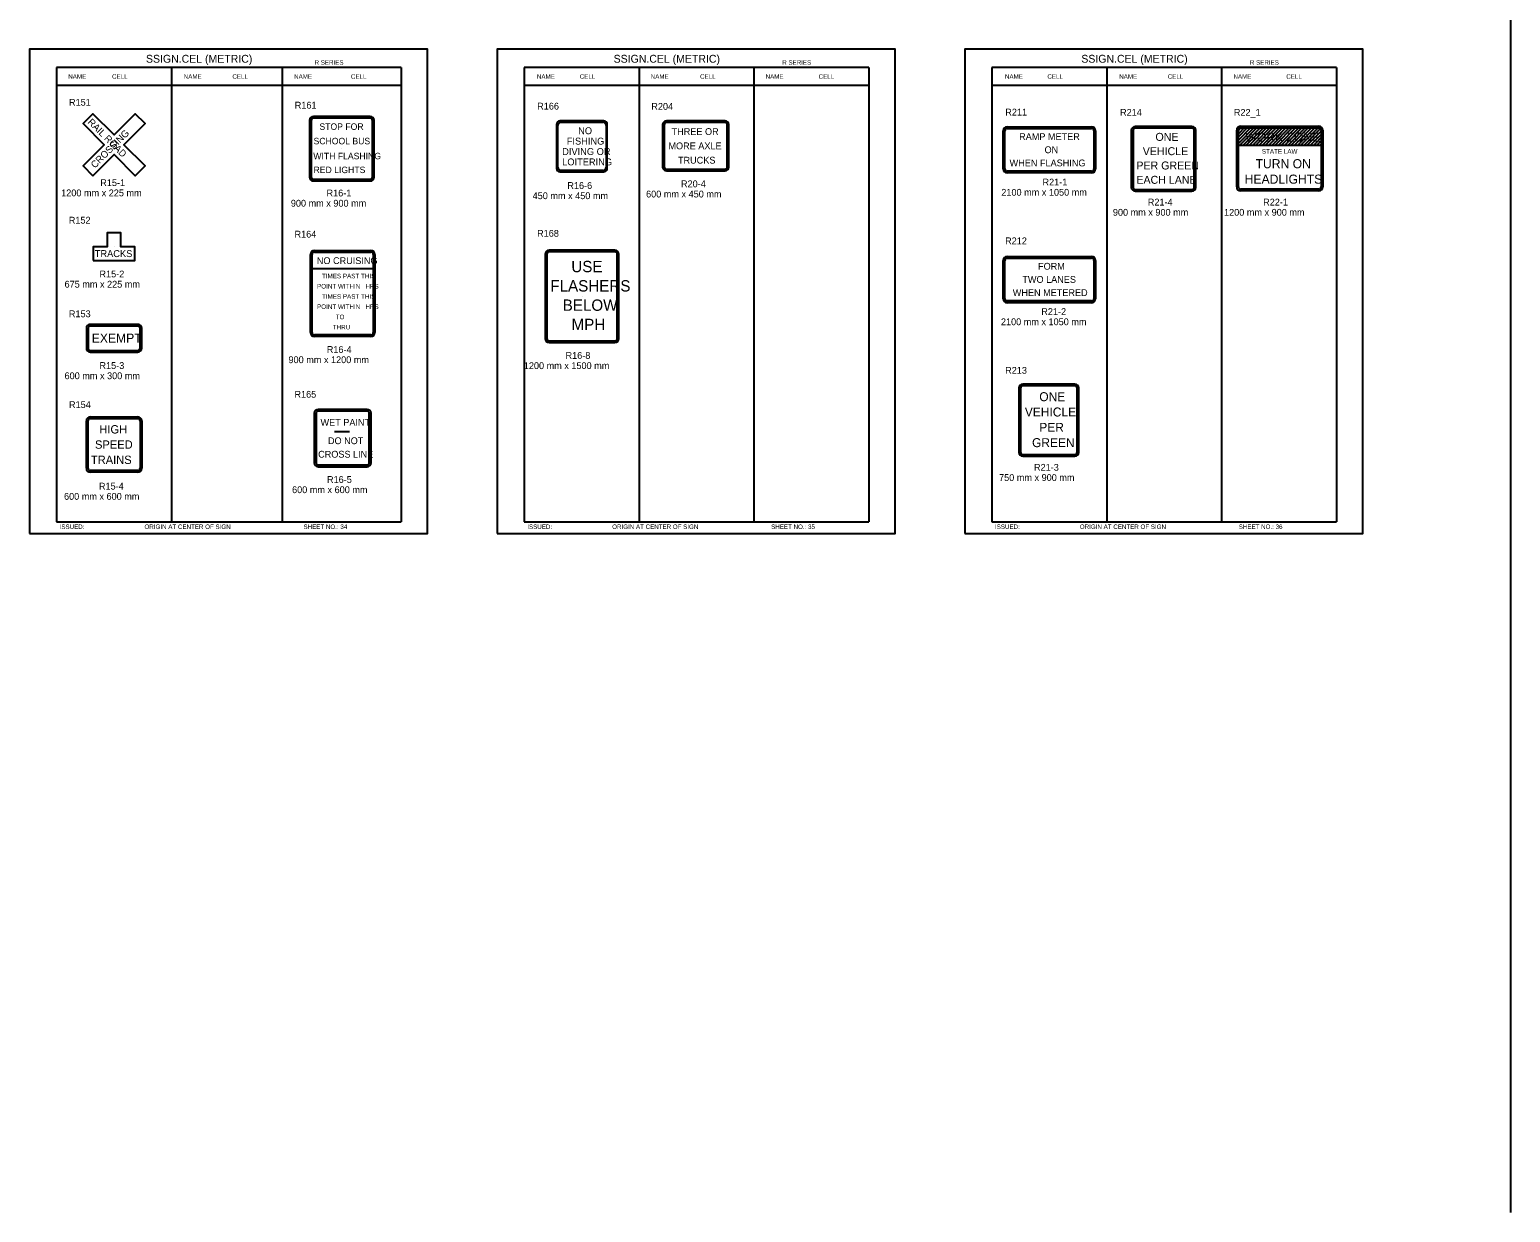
# Model space of a CAD drawing. Extents: x -12 to 6962, y -3756 to 679.
# Drawn here: x 606 to 1258, y -1225 to -705 of the extents above; entities that cross this region are included whole.
import ezdxf

# ---------------------------------------------------------------- set-up
doc = ezdxf.new("R2010")
doc.units = 0
for name, color, linetype in [('Level 1', 7, 'Continuous'), ('Level 2', 7, 'Continuous'), ('Level 3', 7, 'Continuous'), ('Level 63', 7, 'Continuous')]:
    doc.layers.add(name, color=color, linetype=linetype)

msp = doc.modelspace()

# ---------------------------------------------------------------- linework, layer by layer
at = {"layer": 'Level 1'}
for p, q in [((769.73, -721.41), (617.98, -721.41)), ((617.98, -721.41), (617.98, -921.41)), ((668.56, -721.41), (668.56, -921.41)), ((717.35, -721.41), (717.35, -921.41)), ((769.73, -721.41), (769.73, -921.41)), ((975.73, -721.41), (823.97, -721.41)), ((823.97, -721.41), (823.97, -921.41)), ((874.56, -721.41), (874.56, -921.41)), ((925.14, -721.41), (925.14, -921.41)), ((975.73, -721.41), (975.73, -921.41)), ((1181.72, -721.41), (1029.96, -721.41)), ((1029.96, -721.41), (1029.96, -921.41)), ((1080.55, -721.41), (1080.55, -921.41)), ((1131.13, -721.41), (1131.13, -921.41)), ((1181.72, -721.41), (1181.72, -921.41)), ((769.73, -729.33), (617.98, -729.33)), ((975.73, -729.33), (823.97, -729.33)), ((1181.72, -729.33), (1029.96, -729.33)), ((730.14, -744.66), (730.14, -769.61)), ((756.09, -743.66), (731.14, -743.66)), ((757.09, -769.61), (757.09, -744.66)), ((838.75, -765.36), (838.75, -746.86)), ((840.13, -745.48), (858.63, -745.48)), ((860.01, -746.86), (860.01, -765.36)), ((885.62, -746.66), (885.62, -765.12)), ((912.4, -745.66), (886.62, -745.66)), ((913.4, -765.12), (913.4, -746.66)), ((1035.68, -766.08), (1035.68, -749.23)), ((1036.68, -748.23), (1073.89, -748.23)), ((1074.89, -749.23), (1074.89, -766.08)), ((1092.12, -749.13), (1092.12, -774.08)), ((1118.07, -748.13), (1093.12, -748.13)), ((1119.07, -774.08), (1119.07, -749.13)), ((1138.53, -773.97), (1138.53, -749.02)), ((1139.53, -748.02), (1173.96, -748.02)), ((1174.96, -749.02), (1174.96, -773.97)), ((643.29, -755.38), (643.29, -755.38)), ((849.38, -756.11), (849.38, -756.11)), ((743.61, -757.13), (743.61, -757.13)), ((1055.28, -757.66), (1055.28, -757.66)), ((1105.59, -761.6), (1105.59, -761.6)), ((1156.75, -761.5), (1156.75, -761.5)), ((858.63, -766.73), (840.13, -766.73)), ((886.62, -766.12), (912.4, -766.12)), ((1073.89, -767.08), (1036.68, -767.08)), ((731.14, -770.61), (756.09, -770.61)), ((1093.12, -775.08), (1118.07, -775.08)), ((1173.96, -774.97), (1139.53, -774.97)), ((643.29, -800.28), (643.29, -800.28)), ((730.52, -838.09), (730.52, -803.66)), ((731.52, -802.66), (756.47, -802.66)), ((757.47, -803.66), (757.47, -838.09)), ((833.93, -803.59), (833.93, -840.72)), ((863.94, -802.59), (834.93, -802.59)), ((864.94, -840.72), (864.94, -803.59)), ((1035.68, -823.17), (1035.68, -806.31)), ((1036.68, -805.31), (1073.89, -805.31)), ((1074.89, -806.31), (1074.89, -823.17)), ((730.52, -809.93), (757.47, -809.93)), ((1055.28, -814.74), (1055.28, -814.74)), ((743.99, -820.88), (743.99, -820.88)), ((849.43, -822.16), (849.43, -822.16)), ((1073.89, -824.17), (1036.68, -824.17)), ((631.84, -836.21), (631.84, -844.9)), ((653.73, -835.21), (632.84, -835.21)), ((643.29, -840.56), (643.29, -840.56)), ((654.73, -844.9), (654.73, -836.21)), ((756.47, -839.09), (731.52, -839.09)), ((632.84, -845.9), (653.73, -845.9)), ((834.93, -841.72), (863.94, -841.72)), ((1042.58, -862.54), (1042.58, -890.74)), ((1066.48, -861.54), (1043.58, -861.54)), ((1067.48, -890.74), (1067.48, -862.54)), ((732.25, -873.65), (732.25, -895.37)), ((754.73, -872.65), (733.25, -872.65)), ((755.73, -895.37), (755.73, -873.65)), ((631.84, -897.82), (631.84, -876.94)), ((632.84, -875.94), (653.73, -875.94)), ((654.73, -876.94), (654.73, -897.82)), ((1055.03, -876.64), (1055.03, -876.64)), ((740.37, -881.66), (746.99, -881.66)), ((743.99, -884.51), (743.99, -884.51)), ((643.29, -887.38), (643.29, -887.38)), ((1043.58, -891.74), (1066.48, -891.74)), ((653.73, -898.82), (632.84, -898.82)), ((733.25, -896.37), (754.73, -896.37)), ((617.98, -921.41), (769.73, -921.41)), ((823.97, -921.41), (975.73, -921.41)), ((1029.96, -921.41), (1181.72, -921.41))]:
    msp.add_line(p, q, dxfattribs=at)
for points in [[(633.95, -769.03), (643.28, -759.7), (652.62, -769.03), (656.93, -764.72), (647.6, -755.39), (656.93, -746.05), (652.62, -741.74), (643.28, -751.07), (633.95, -741.74), (629.64, -746.05), (638.97, -755.39), (629.64, -764.72)], [(634.14, -806.37), (652.43, -806.37), (652.43, -800.28), (646.33, -800.28), (646.33, -794.18), (640.24, -794.18), (640.24, -800.28), (634.14, -800.28)]]:
    msp.add_lwpolyline(points, close=True, dxfattribs=at)
for centre, radius, start, end in [((731.14, -744.66), 1, 90, 180), ((756.09, -744.66), 1, 0, 90), ((840.13, -746.86), 1.38, 90, 180), ((858.63, -746.86), 1.38, 0, 90), ((886.62, -746.66), 1, 90, 180), ((912.4, -746.66), 1, 0, 90), ((1036.68, -749.23), 1, 90, 180), ((1073.89, -749.23), 1, 0, 90), ((1093.12, -749.13), 1, 90, 180), ((1118.07, -749.13), 1, 0, 90), ((1139.53, -749.02), 1, 90, 180), ((1173.96, -749.02), 1, 0, 90), ((731.14, -769.61), 1, 180, 270), ((756.09, -769.61), 1, 270, 0), ((840.13, -765.36), 1.38, 180, 270), ((858.63, -765.36), 1.38, 270, 0), ((886.62, -765.12), 1, 180, 270), ((912.4, -765.12), 1, 270, 0), ((1036.68, -766.08), 1, 180, 270), ((1073.89, -766.08), 1, 270, 0), ((1093.12, -774.08), 1, 180, 270), ((1118.07, -774.08), 1, 270, 0), ((1139.53, -773.97), 1, 180, 270), ((1173.96, -773.97), 1, 270, 0), ((731.52, -803.66), 1, 90, 180), ((756.47, -803.66), 1, 0, 90), ((834.93, -803.59), 1, 90, 180), ((863.94, -803.59), 1, 0, 90), ((1036.68, -806.31), 1, 90, 180), ((1073.89, -806.31), 1, 0, 90), ((1036.68, -823.17), 1, 180, 270), ((1073.89, -823.17), 1, 270, 0), ((632.84, -836.21), 1, 90, 180), ((653.73, -836.21), 1, 0, 90), ((731.52, -838.09), 1, 180, 270), ((756.47, -838.09), 1, 270, 0), ((834.93, -840.72), 1, 180, 270), ((863.94, -840.72), 1, 270, 0), ((632.84, -844.9), 1, 180, 270), ((653.73, -844.9), 1, 270, 0), ((1043.58, -862.54), 1, 90, 180), ((1066.48, -862.54), 1, 0, 90), ((733.25, -873.65), 1, 90, 180), ((754.73, -873.65), 1, 0, 90), ((632.84, -876.94), 1, 90, 180), ((653.73, -876.94), 1, 0, 90), ((1043.58, -890.74), 1, 180, 270), ((1066.48, -890.74), 1, 270, 0), ((632.84, -897.82), 1, 180, 270), ((653.73, -897.82), 1, 270, 0), ((733.25, -895.37), 1, 180, 270), ((754.73, -895.37), 1, 270, 0)]:
    msp.add_arc(centre, radius, start, end, dxfattribs=at)
at = {"layer": 'Level 3'}
for p, q in [((1258.34, 661.66), (1258.34, -1225.34)), ((756.09, -742.91), (731.14, -742.91)), ((729.39, -744.66), (729.39, -769.61)), ((757.84, -769.61), (757.84, -744.66)), ((838.2, -746.42), (838.2, -765.8)), ((859.07, -744.93), (839.69, -744.93)), ((860.56, -765.8), (860.56, -746.42)), ((884.87, -746.66), (884.87, -765.12)), ((912.4, -744.91), (886.62, -744.91)), ((914.15, -765.12), (914.15, -746.66)), ((1034.93, -766.08), (1034.93, -749.23)), ((1036.68, -747.48), (1073.89, -747.48)), ((1075.64, -749.23), (1075.64, -766.08)), ((1091.37, -749.13), (1091.37, -774.08)), ((1118.07, -747.38), (1093.12, -747.38)), ((1119.82, -774.08), (1119.82, -749.13)), ((1146.03, -747.27), (1137.78, -755.52)), ((1140.37, -747.27), (1137.78, -749.86)), ((1141.79, -747.27), (1137.78, -751.28)), ((1143.2, -747.27), (1137.78, -752.69)), ((1144.61, -747.27), (1137.78, -754.11)), ((1137.78, -773.97), (1137.78, -749.02)), ((1138.8, -747.43), (1137.94, -748.29)), ((1147.44, -747.27), (1139.19, -755.52)), ((1139.53, -747.27), (1173.96, -747.27)), ((1148.86, -747.27), (1140.61, -755.52)), ((1150.27, -747.27), (1142.02, -755.52)), ((1151.69, -747.27), (1143.44, -755.52)), ((1153.1, -747.27), (1144.85, -755.52)), ((1154.51, -747.27), (1146.26, -755.52)), ((1155.93, -747.27), (1147.68, -755.52)), ((1157.34, -747.27), (1149.09, -755.52)), ((1158.76, -747.27), (1150.51, -755.52)), ((1160.17, -747.27), (1151.92, -755.52)), ((1161.59, -747.27), (1153.34, -755.52)), ((1163, -747.27), (1154.75, -755.52)), ((1164.41, -747.27), (1156.16, -755.52)), ((1165.83, -747.27), (1157.58, -755.52)), ((1167.24, -747.27), (1158.99, -755.52)), ((1168.66, -747.27), (1160.41, -755.52)), ((1170.07, -747.27), (1161.82, -755.52)), ((1171.48, -747.27), (1163.24, -755.52)), ((1172.9, -747.27), (1164.65, -755.52)), ((1174.28, -747.3), (1166.06, -755.52)), ((1175.21, -747.79), (1167.48, -755.52)), ((1175.69, -748.73), (1168.89, -755.52)), ((1175.71, -749.02), (1175.71, -773.97)), ((899.51, -755.89), (899.51, -755.89)), ((1137.78, -755.52), (1175.71, -755.52)), ((1175.71, -750.12), (1170.31, -755.52)), ((1175.71, -751.53), (1171.72, -755.52)), ((1175.71, -752.94), (1173.13, -755.52)), ((1175.71, -754.36), (1174.55, -755.52)), ((839.69, -767.29), (859.07, -767.29)), ((886.62, -766.87), (912.4, -766.87)), ((1073.89, -767.83), (1036.68, -767.83)), ((731.14, -771.36), (756.09, -771.36)), ((1093.12, -775.83), (1118.07, -775.83)), ((1173.96, -775.72), (1139.53, -775.72)), ((731.52, -801.91), (756.47, -801.91)), ((863.94, -801.84), (834.93, -801.84)), ((729.77, -838.09), (729.77, -803.66)), ((758.22, -803.66), (758.22, -838.09)), ((833.18, -803.59), (833.18, -840.72)), ((865.69, -840.72), (865.69, -803.59)), ((1034.93, -823.17), (1034.93, -806.31)), ((1036.68, -804.56), (1073.89, -804.56)), ((1075.64, -806.31), (1075.64, -823.17)), ((1073.89, -824.92), (1036.68, -824.92)), ((653.73, -834.46), (632.84, -834.46)), ((631.09, -836.21), (631.09, -844.9)), ((655.48, -844.9), (655.48, -836.21)), ((756.47, -839.84), (731.52, -839.84)), ((632.84, -846.65), (653.73, -846.65)), ((834.93, -842.47), (863.94, -842.47)), ((1066.48, -860.79), (1043.58, -860.79)), ((1041.83, -862.54), (1041.83, -890.74)), ((1068.23, -890.74), (1068.23, -862.54)), ((731.5, -873.65), (731.5, -895.37)), ((754.73, -871.9), (733.25, -871.9)), ((756.48, -895.37), (756.48, -873.65)), ((631.09, -897.82), (631.09, -876.94)), ((632.84, -875.19), (653.73, -875.19)), ((655.48, -876.94), (655.48, -897.82)), ((1043.58, -892.49), (1066.48, -892.49)), ((653.73, -899.57), (632.84, -899.57)), ((733.25, -897.12), (754.73, -897.12)), ((1258.34, -1225.34), (1258.34, -1225.34))]:
    msp.add_line(p, q, dxfattribs=at)
for centre, radius, start, end in [((731.14, -744.66), 1.75, 90, 180), ((756.09, -744.66), 1.75, 0, 90), ((839.69, -746.42), 1.49, 90, 180), ((859.07, -746.42), 1.49, 0, 90), ((886.62, -746.66), 1.75, 90, 180), ((912.4, -746.66), 1.75, 0, 90), ((1036.68, -749.23), 1.75, 90, 180), ((1073.89, -749.23), 1.75, 0, 90), ((1093.12, -749.13), 1.75, 90, 180), ((1118.07, -749.13), 1.75, 0, 90), ((1139.53, -749.02), 1.75, 90, 180), ((1173.96, -749.02), 1.75, 0, 90), ((731.14, -769.61), 1.75, 180, 270), ((756.09, -769.61), 1.75, 270, 0), ((839.69, -765.8), 1.49, 180, 270), ((859.07, -765.8), 1.49, 270, 0), ((886.62, -765.12), 1.75, 180, 270), ((912.4, -765.12), 1.75, 270, 0), ((1036.68, -766.08), 1.75, 180, 270), ((1073.89, -766.08), 1.75, 270, 0), ((1093.12, -774.08), 1.75, 180, 270), ((1118.07, -774.08), 1.75, 270, 0), ((1139.53, -773.97), 1.75, 180, 270), ((1173.96, -773.97), 1.75, 270, 0), ((731.52, -803.66), 1.75, 90, 180), ((756.47, -803.66), 1.75, 0, 90), ((834.93, -803.59), 1.75, 90, 180), ((863.94, -803.59), 1.75, 0, 90), ((1036.68, -806.31), 1.75, 90, 180), ((1073.89, -806.31), 1.75, 0, 90), ((1036.68, -823.17), 1.75, 180, 270), ((1073.89, -823.17), 1.75, 270, 0), ((632.84, -836.21), 1.75, 90, 180), ((653.73, -836.21), 1.75, 0, 90), ((731.52, -838.09), 1.75, 180, 270), ((756.47, -838.09), 1.75, 270, 0), ((834.93, -840.72), 1.75, 180, 270), ((863.94, -840.72), 1.75, 270, 0), ((632.84, -844.9), 1.75, 180, 270), ((653.73, -844.9), 1.75, 270, 0), ((1043.58, -862.54), 1.75, 90, 180), ((1066.48, -862.54), 1.75, 0, 90), ((733.25, -873.65), 1.75, 90, 180), ((754.73, -873.65), 1.75, 0, 90), ((632.84, -876.94), 1.75, 90, 180), ((653.73, -876.94), 1.75, 0, 90), ((1043.58, -890.74), 1.75, 180, 270), ((1066.48, -890.74), 1.75, 270, 0), ((632.84, -897.82), 1.75, 180, 270), ((653.73, -897.82), 1.75, 270, 0), ((733.25, -895.37), 1.75, 180, 270), ((754.73, -895.37), 1.75, 270, 0)]:
    msp.add_arc(centre, radius, start, end, dxfattribs=at)
at = {"layer": 'Level 63'}
for points in [[(606.1, -926.46), (781.36, -926.46), (781.36, -713.36), (606.1, -713.36)], [(812.09, -926.46), (987.36, -926.46), (987.36, -713.36), (812.09, -713.36)], [(1018.09, -926.46), (1193.35, -926.46), (1193.35, -713.36), (1018.09, -713.36)]]:
    msp.add_lwpolyline(points, close=True, dxfattribs=at)

# ---------------------------------------------------------------- texts
at = {"layer": 'Level 1'}
for s, rotation, p in [('RAIL ROAD', 315, (631.46, -745.71)), ('CROSSING', 45, (634.86, -765.97))]:
    msp.add_text(s, height=3.048, rotation=rotation, dxfattribs=at).set_placement(p)
for s, height, p in [('STOP FOR', 2.845, (733.76, -748.85)), ('NO', 3.048, (847.72, -750.77)), ('THREE OR', 3, (888.88, -751.11)), ('WORK ZONE', 4, (1141.62, -754.06)), ('SCHOOL BUS', 2.845, (731.16, -755.2)), ('FISHING', 3.048, (842.71, -755.34)), ('MORE AXLE', 3, (887.49, -757.41)), ('RAMP METER', 3, (1041.95, -753.32)), ('ON', 3, (1053.15, -759.12)), ('VEHICLE', 3.5, (1096.41, -759.99)), ('ONE', 3.5, (1102.01, -753.69)), ('WITH FLASHING', 2.8449, (731.07, -761.79)), ('DIVING OR', 3.048, (840.69, -759.92)), ('LOITERING', 3.048, (840.69, -764.49)), ('TRUCKS', 3, (891.69, -763.71)), ('WHEN FLASHING', 3, (1037.75, -764.92)), ('PER GREEN', 3.5, (1093.6, -766.29)), ('TURN ON', 4, (1146.1, -765.75)), ('STATE LAW', 2, (1148.89, -759.34)), ('RED LIGHTS', 2.845, (731.16, -767.89)), ('EACH LANE', 3.5, (1093.61, -772.59)), ('HEADLIGHTS', 4, (1141.31, -772.55)), ('TRACKS', 3.048, (634.8, -804.85)), ('USE', 5, (844.71, -811.51)), ('FORM', 3, (1050.28, -810.4)), ('FLASHERS', 5, (835.46, -820.01)), ('TWO LANES', 3, (1043.36, -816.2)), ('WHEN METERED', 3, (1039.15, -822)), ('BELOW', 5, (840.9, -828.51)), ('   MPH', 5, (839.24, -837.01)), ('EXEMPT', 4, (633.46, -842.53)), ('ONE', 3.944, (1050.84, -868.28)), ('VEHICLE', 3.944, (1044.47, -875.02)), ('HIGH', 3.657, (636.82, -882.5)), ('WET PAINT', 3, (734.24, -879.12)), ('PER', 3.944, (1050.83, -881.76)), ('SPEED', 3.657, (634.91, -889.21)), ('DO NOT', 3, (737.51, -887.2)), ('GREEN', 3.944, (1047.64, -888.51)), ('TRAINS', 3.657, (633.11, -895.91)), ('CROSS LINE', 3, (733.19, -893.14))]:
    msp.add_text(s, height=height, dxfattribs=at).set_placement(p)
at = {"layer": 'Level 2'}
for s, height, p in [('R151', 3, (623.45, -738.21)), ('R161', 3, (722.88, -739.49)), ('R166', 3, (829.68, -739.92)), ('R204', 3, (879.94, -740.03)), ('R211', 3, (1035.85, -742.56)), ('R214', 3, (1086.41, -742.65)), ('R22_1', 3, (1136.53, -742.65)), ('1200 mm x 225 mm', 3, (620, -778.1)), ('R15-1', 3, (637.22, -773.6)), ('R16-1', 3, (736.89, -778.15)), ('R16-6', 3, (842.96, -774.85)), ('600 mm x 450 mm', 3, (877.64, -778.61)), ('R20-4', 3, (893.01, -774.11)), ('2100 mm x 1050 mm', 3, (1034.11, -777.84)), ('R21-1', 3, (1052.24, -773.34)), ('900 mm x 900 mm', 3, (721.17, -782.65)), ('450 mm x 450 mm', 3, (827.67, -779.35)), ('R21-4', 3, (1098.63, -782.15)), ('R22-1', 3, (1149.44, -782.15)), ('R152', 3, (623.36, -790.12)), ('900 mm x 900 mm', 3, (1083.25, -786.65)), ('1200 mm x 900 mm', 3, (1132.22, -786.65)), ('R164', 3, (722.79, -796.27)), ('R168', 3, (829.63, -795.9)), ('R212', 3, (1035.78, -799.21)), ('NO CRUISING', 3, (732.61, -807.93)), ('675 mm x 225 mm', 3, (621.49, -818.3)), ('R15-2', 3, (636.87, -813.8)), ('  TIMES PAST THIS', 2, (733.35, -814.19)), ('POINT WITHIN   HRS', 2, (732.7, -818.69)), ('  TIMES PAST THIS', 2, (733.35, -823.19)), ('R153', 3, (623.4, -831.33)), ('POINT WITHIN   HRS', 2, (732.7, -827.69)), ('R21-2', 3, (1051.72, -830.34)), ('    THRU    ', 2, (736.57, -836.69)), ('    TO    ', 2, (737.87, -832.19)), ('2100 mm x 1050 mm', 3, (1033.94, -834.84)), ('R16-4', 3, (737, -847.04)), ('R16-8', 3, (842.16, -849.65)), ('R15-3', 3, (636.87, -854.1)), ('900 mm x 1200 mm', 3, (720.13, -851.54)), ('1200 mm x 1500 mm', 3, (823.78, -854.15)), ('R213', 3, (1035.8, -856.2)), ('600 mm x 300 mm', 3, (621.49, -858.6)), ('R165', 3, (722.76, -866.76)), ('R154', 3, (623.45, -871.31)), ('R21-3', 3, (1048.5, -898.9)), ('R15-4', 3, (636.63, -907.19)), ('600 mm x 600 mm', 3, (721.71, -908.76)), ('R16-5', 3, (737.09, -904.26)), ('750 mm x 900 mm', 3, (1033.12, -903.4)), ('600 mm x 600 mm', 3, (621.26, -911.69))]:
    msp.add_text(s, height=height, dxfattribs=at).set_placement(p)
at = {"layer": 'Level 3'}
for s, height, p in [('SSIGN.CEL (METRIC)', 3.4642, (657.36, -719.3)), ('SSIGN.CEL (METRIC)', 3.4642, (863.35, -719.3)), ('SSIGN.CEL (METRIC)', 3.4642, (1069.35, -719.3)), ('R SERIES', 1.979, (731.61, -720.17)), ('R SERIES', 1.979, (937.6, -720.17)), ('R SERIES', 1.979, (1143.59, -720.17)), ('NAME', 1.98, (623.14, -726.37)), ('CELL', 1.98, (642.41, -726.37)), ('NAME', 1.98, (673.99, -726.37)), ('CELL', 1.98, (695.43, -726.37)), ('NAME', 1.98, (722.62, -726.37)), ('CELL', 1.98, (747.64, -726.37)), ('NAME', 1.98, (829.55, -726.37)), ('CELL', 1.98, (848.4, -726.37)), ('NAME', 1.98, (879.68, -726.37)), ('CELL', 1.98, (901.42, -726.37)), ('NAME', 1.98, (930.28, -726.37)), ('CELL', 1.98, (953.63, -726.37)), ('NAME', 1.98, (1035.71, -726.37)), ('CELL', 1.98, (1054.4, -726.37)), ('NAME', 1.98, (1086.04, -726.37)), ('CELL', 1.98, (1107.42, -726.37)), ('NAME', 1.98, (1136.37, -726.37)), ('CELL', 1.98, (1159.62, -726.37)), ('ISSUED:', 1.98, (619.32, -924.53)), ('ORIGIN AT CENTER OF SIGN', 1.9795, (656.7, -924.53)), ('SHEET NO.: 34', 1.9795, (726.74, -924.53)), ('ISSUED:', 1.98, (825.31, -924.53)), ('ORIGIN AT CENTER OF SIGN', 1.9795, (862.7, -924.53)), ('SHEET NO.: 35', 1.9795, (932.73, -924.53)), ('ISSUED:', 1.98, (1031.31, -924.53)), ('ORIGIN AT CENTER OF SIGN', 1.9795, (1068.69, -924.53)), ('SHEET NO.: 36', 1.9795, (1138.67, -924.53))]:
    msp.add_text(s, height=height, dxfattribs=at).set_placement(p)

doc.saveas('drawing.dxf')
